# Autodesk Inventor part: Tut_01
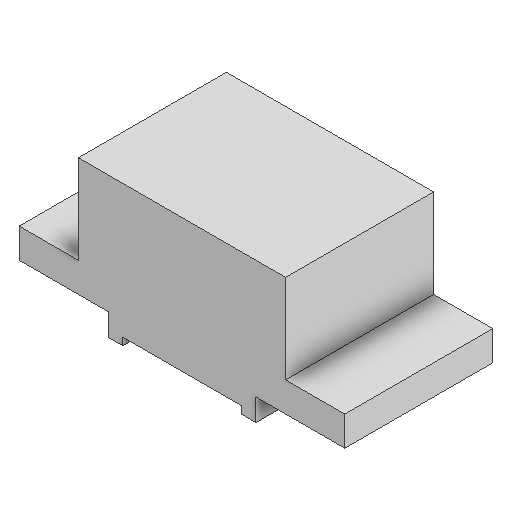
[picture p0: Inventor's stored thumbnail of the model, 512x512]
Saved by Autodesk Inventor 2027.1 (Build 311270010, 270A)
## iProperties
Created: 2022-07
Part Number: Tut_01
Material: Generic
Document SubType Name: Modeling
Designer: LENOVO-CADCIM
Density: 1 g/cm^3
Appearance: Default
Author: LENOVO-CADCIM
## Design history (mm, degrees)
sketch "Sketch1"
  geometry: L1 (0, 0)-(50.8, 0); L2 (50.8, 0)-(50.8, -6.35); L3 (50.8, -6.35)-(63.5, -6.35); L4 (63.5, -6.35)-(63.5, 12.7); L5 (63.5, 12.7)-(139.7, 12.7); L6 (139.7, 12.7)-(139.7, 38.1); L7 (139.7, 38.1)-(88.9, 38.1); L8 (88.9, 38.1)-(88.9, 114.3); L9 (88.9, 114.3)-(-88.9, 114.3); L10 (-88.9, 114.3)-(-88.9, 38.1); L11 (-88.9, 38.1)-(-139.7, 38.1); L12 (-139.7, 38.1)-(-139.7, 12.7); L13 (-139.7, 12.7)-(-63.5, 12.7); L14 (-63.5, 12.7)-(-63.5, -6.35); L15 (-63.5, -6.35)-(-50.8, -6.35); L16 (-50.8, -6.35)-(-50.8, 0); L17 (-50.8, 0)-(0, 0)
  constraints: 34 end point, 12 perpendicular, 2 point on line, 1 horizontal, 1 vertical
  dimensions: "d0" = 50.8 distance of L1.start L1.end; "d1" = 6.35 distance of L1.end L2.end; "d2" = 12.7 distance of L2.end L3.end; "d3" = 19.05 distance of L3.end L4.end; "d4" = 76.2 distance of L4.end L5.end; "d5" = 25.4 distance of L5.end L6.end; "d6" = 50.8 distance of L6.end L7.end; "d7" = 76.2 distance of L7.end L8.end; "d8" = 177.8 distance of L8.end L9.end; "d9" = 76.2 distance of L9.end L10.end; "d10" = 50.8 distance of L10.end L11.end; "d12" = 25.4 distance of L11.end L12.end; "d13" = 76.2 distance of L12.end L13.end; "d14" = 19.05 distance of L13.end L14.end; "d15" = 12.7 distance of L14.end L15.end; "d16" = 6.35 distance of L15.end L16.end; "d17" = 50.8 distance of L16.end L1.start (derived)
extrude "Extrusion1" new body sketch "Sketch1" distance "d18" = 127; taper "d19" = 0 deg
body "Solid1"
